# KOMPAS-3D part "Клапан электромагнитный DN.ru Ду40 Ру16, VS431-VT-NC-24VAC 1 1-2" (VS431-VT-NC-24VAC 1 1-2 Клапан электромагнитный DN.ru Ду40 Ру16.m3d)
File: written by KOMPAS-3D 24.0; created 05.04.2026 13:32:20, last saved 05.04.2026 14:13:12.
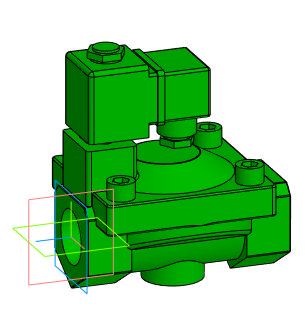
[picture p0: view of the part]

Document properties: Автор: artio; Полное имя файла: C:\Users\artio\OneDrive\Рабочий стол\Клапан электромагнитный DN.ru\VS431\VS431-VT-NC\VS431-VT-NC-24VAC\Ду40\VS431-VT-NC-24VAC 1 1-2 Клапан электромагнитный DN.ru Ду40 Ру16.m3d

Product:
- Body: Тело 1  | qty 1
    Масса: 3.859459
- Part/product: Клапан электромагнитный DN.ru Ду40 Ру16  | designation VS431-VT-NC-24VAC 1 1-2
    Масса: 2.285
    Раздел спецификации: Прочие изделия
    Примечание: D130-05516
    additional columns: ef56311e-7521-43dc-8291-0e6108b3d81d; artio; c; Шероховатость не задана; Да

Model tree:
1. Операция без истории:1

Expressions: VS431-VT-NC-24VAC 1 1-2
